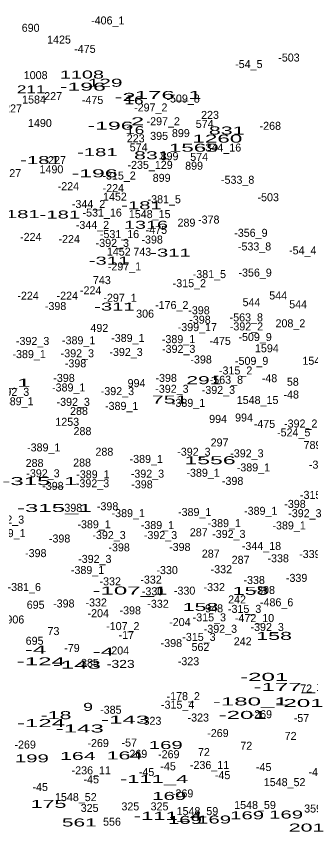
# Model space of a CAD drawing. Extents: x -660434 to -656144, y -997850 to -994016.
# Drawn here: x -658565.3 to -658418.1, y -996493.8 to -996086.2 of the extents above; entities that cross this region are included whole.
import ezdxf
from ezdxf.enums import TextEntityAlignment as Align

# ---------------------------------------------------------------- set-up
doc = ezdxf.new("R2010")
doc.units = 0
doc.header["$LTSCALE"] = 1.6
doc.layers.add('24', color=7, linetype='Continuous')

msp = doc.modelspace()

# ---------------------------------------------------------------- texts
at = {"layer": '24'}
for s, p in [('-406_1', (-658519.59, -996090.28)), ('690', (-658558.142, -996093.96)), ('1425', (-658543.954, -996099.84)), ('-475', (-658531.005, -996104.48)), ('-54_5', (-658449.047, -996112.1)), ('-503', (-658428.989, -996108.82)), ('1008', (-658555.638, -996117.62)), ('-227', (-658547.781, -996128.11)), ('1584', (-658556.454, -996129.81)), ('-475', (-658527.165, -996130.03)), ('-509_8', (-658481.932, -996129.33)), ('-227', (-658567.841, -996134.26)), ('-297_2', (-658498.084, -996133.76)), ('-297_2', (-658491.844, -996140.67)), ('223', (-658468.457, -996137.51)), ('1490', (-658553.514, -996141.54)), ('574', (-658471.127, -996141.99)), ('-268', (-658438.31, -996142.96)), ('223', (-658505.617, -996149.22)), ('395', (-658493.903, -996147.98)), ('899', (-658483.048, -996146.59)), ('574', (-658504.147, -996153.71)), ('-344_16', (-658462.679, -996153.83)), ('-227', (-658545.861, -996160.09)), ('899', (-658488.708, -996158.13)), ('574', (-658473.877, -996158.48)), ('1490', (-658547.754, -996164.69)), ('-235_129', (-658498.421, -996162.49)), ('899', (-658476.418, -996162.92)), ('-227', (-658568.231, -996166.62)), ('-315_2', (-658513.926, -996167.82)), ('899', (-658492.648, -996168.97)), ('-224', (-658539.269, -996173.13)), ('-533_8', (-658454.642, -996169.93)), ('-224', (-658516.799, -996174.09)), ('1452', (-658516.004, -996178.38)), ('-381_5', (-658491.346, -996179.65)), ('-503', (-658439.359, -996178.66)), ('-344_2', (-658529.201, -996182.04)), ('-531_16', (-658522.375, -996186.32)), ('1548_15', (-658498.626, -996187.08)), ('-378', (-658469.081, -996189.81)), ('-344_2', (-658527.241, -996192.5)), ('289', (-658480.233, -996191.35)), ('-531_16', (-658513.725, -996197.07)), ('-475', (-658495.285, -996194.95)), ('-356_9', (-658448.023, -996196.44)), ('-224', (-658558.079, -996198.49)), ('-224', (-658538.879, -996199.55)), ('-392_3', (-658517.308, -996201.48)), ('-398', (-658497.39, -996199.81)), ('1452', (-658514.084, -996205.84)), ('743', (-658502.337, -996205.93)), ('-533_8', (-658446.192, -996203.25)), ('-54_4', (-658422.091, -996205.2)), ('-297_1', (-658511.227, -996213.23)), ('-381_5', (-658468.786, -996217.08)), ('-356_9', (-658445.903, -996216.32)), ('743', (-658522.547, -996220.07)), ('-315_2', (-658478.796, -996221.61)), ('-224', (-658528.129, -996225.18)), ('-224', (-658559.429, -996227.87)), ('-224', (-658539.839, -996227.87)), ('-297_1', (-658513.437, -996228.89)), ('544', (-658434.376, -996227.75)), ('-398', (-658545.68, -996233.04)), ('-176_2', (-658487.597, -996232.52)), ('544', (-658447.716, -996231.11)), ('544', (-658424.396, -996232.16)), ('306', (-658500.927, -996236.85)), ('-398', (-658473.96, -996235.14)), ('-563_8', (-658450.328, -996238.68)), ('-398', (-658473.48, -996239.86)), ('208_2', (-658428.259, -996241.67)), ('492', (-658523.797, -996243.99)), ('-399_17', (-658474.801, -996243.57)), ('-392_2', (-658450.228, -996243.22)), ('-392_3', (-658557.168, -996250.5)), ('-389_1', (-658534.132, -996250.15)), ('-389_1', (-658509.552, -996249)), ('-389_1', (-658484.212, -996249.58)), ('-475', (-658463.405, -996250.46)), ('-509_9', (-658445.907, -996248.53)), ('-392_3', (-658484.118, -996254.45)), ('1594', (-658440.02, -996254.14)), ('-389_1', (-658558.902, -996257.07)), ('-392_3', (-658534.798, -996256.65)), ('-392_3', (-658510.448, -996255.99)), ('-398', (-658535.7, -996261.66)), ('-398', (-658472.91, -996259.74)), ('-509_9', (-658447.637, -996260.44)), ('1548_24', (-658411.847, -996260.39)), ('-315_2', (-658455.656, -996265.24)), ('-398', (-658541.46, -996268.96)), ('994', (-658505.193, -996271.55)), ('-398', (-658490.38, -996268.96)), ('-563_8', (-658460.288, -996269.88)), ('-48', (-658438.709, -996269.11)), ('58', (-658427.047, -996270.88)), ('-389_1', (-658539.122, -996273.73)), ('-392_3', (-658514.768, -996275.55)), ('-392_3', (-658487.498, -996274.4)), ('-392_3', (-658464.268, -996274.97)), ('-392_3', (-658567.188, -996275.93)), ('-48', (-658427.859, -996277.27)), ('-389_1', (-658565.042, -996280.65)), ('-392_3', (-658536.848, -996280.93)), ('-389_1', (-658512.622, -996282.95)), ('-389_1', (-658479.212, -996281.42)), ('1548_15', (-658444.676, -996280)), ('288', (-658533.977, -996285.47)), ('1253', (-658539.85, -996290.91)), ('994', (-658464.413, -996289.44)), ('994', (-658451.453, -996288.76)), ('-392_2', (-658423.098, -996291.76)), ('288', (-658532.237, -996295.57)), ('-475', (-658441.235, -996291.94)), ('-524_5', (-658426.607, -996296.19)), ('-389_1', (-658551.602, -996303.7)), ('297', (-658463.688, -996301.22)), ('789', (-658417.208, -996302.48)), ('288', (-658521.277, -996305.85)), ('-392_3', (-658476.518, -996305.87)), ('-392_3', (-658450.018, -996306.64)), ('288', (-658556.177, -996311.47)), ('288', (-658532.427, -996311.28)), ('-389_1', (-658500.332, -996309.46)), ('-374_3', (-658410.692, -996312.31)), ('-389_1', (-658471.922, -996316.37)), ('-389_1', (-658446.762, -996313.69)), ('-392_3', (-658551.978, -996316.63)), ('-389_1', (-658527.022, -996317.14)), ('-392_3', (-658499.748, -996316.82)), ('-398', (-658457.16, -996320.43)), ('-398', (-658547.02, -996322.93)), ('-392_3', (-658527.208, -996321.62)), ('-398', (-658502.48, -996322.16)), ('-315_2', (-658415.146, -996327.43)), ('-398', (-658425.97, -996331.94)), ('-398', (-658537.72, -996333.87)), ('-398', (-658519.67, -996333.1)), ('-389_1', (-658509.342, -996336.54)), ('-389_1', (-658476.122, -996335.97)), ('-389_1', (-658443.102, -996335.39)), ('-392_3', (-658421.028, -996336.58)), ('-392_3', (-658569.708, -996339.77)), ('-389_1', (-658526.432, -996342.11)), ('-389_1', (-658494.752, -996342.5)), ('-389_1', (-658461.342, -996341.54)), ('-389_1', (-658428.912, -996342.69)), ('-389_1', (-658569.012, -996346.53)), ('-392_3', (-658518.948, -996347.52)), ('-392_3', (-658493.218, -996347.52)), ('287', (-658474.093, -996346.11)), ('-392_3', (-658459.048, -996346.95)), ('-398', (-658543.67, -996349.23)), ('-344_18', (-658442.724, -996352.95)), ('-398', (-658555.58, -996356.54)), ('-398', (-658513.91, -996353.65)), ('-398', (-658483.57, -996353.46)), ('287', (-658468.083, -996356.78)), ('-339', (-658418.54, -996357)), ('-392_3', (-658526.058, -996359.43)), ('287', (-658453.163, -996359.88)), ('-338', (-658434.375, -996359.11)), ('-389_1', (-658529.692, -996364.97)), ('-330', (-658489.899, -996365.03)), ('-332', (-658462.795, -996364.58)), ('-339', (-658425.16, -996368.91)), ('-332', (-658518.355, -996370.63)), ('-332', (-658497.935, -996369.76)), ('-338', (-658446.375, -996369.97)), ('-381_6', (-658561.342, -996373.48)), ('-330', (-658497.189, -996375.6)), ('-330', (-658481.169, -996375.29)), ('-332', (-658466.355, -996373.51)), ('-398', (-658441.33, -996374.97)), ('-332', (-658525.365, -996381.19)), ('242', (-658454.931, -996379.68)), ('-486_6', (-658435.148, -996381.12)), ('695', (-658555.638, -996382.34)), ('-398', (-658541.56, -996381.7)), ('-398', (-658508.34, -996385.15)), ('-332', (-658494.455, -996381.86)), ('948', (-658466.397, -996384.15)), ('-315_3', (-658451.156, -996384.41)), ('906', (-658565.802, -996389.7)), ('-204', (-658524.333, -996386.57)), ('-315_3', (-658468.796, -996388.64)), ('-472_10', (-658446.209, -996389)), ('-107_2', (-658512.056, -996393.01)), ('-204', (-658483.523, -996390.99)), ('-392_3', (-658439.878, -996393.47)), ('73', (-658546.733, -996395.5)), ('-17', (-658510.29, -996397.43)), ('-392_3', (-658463.268, -996394.37)), ('695', (-658556.168, -996400.35)), ('-398', (-658487.79, -996401.48)), ('-315_3', (-658473.986, -996398.43)), ('242', (-658452.121, -996400.62)), ('-79', (-658537.485, -996403.97)), ('-204', (-658514.253, -996405.2)), ('562', (-658473.243, -996403.46)), ('-385', (-658529.375, -996411.4)), ('-323', (-658479.225, -996410.57)), ('72', (-658420.383, -996424.19)), ('-178_2', (-658481.842, -996428.03)), ('-315_4', (-658484.64, -996432.3)), ('-385', (-658518.045, -996434.83)), ('-269', (-658442.805, -996437.06)), ('-323', (-658498.135, -996440.34)), ('-323', (-658474.325, -996438.71)), ('-57', (-658422.721, -996438.95)), ('-269', (-658464.495, -996446.47)), ('72', (-658428.163, -996447.91)), ('-269', (-658560.885, -996452.23)), ('-269', (-658524.405, -996451.47)), ('-57', (-658508.841, -996451.24)), ('72', (-658450.333, -996452.81)), ('-269', (-658505.205, -996456.84)), ('-269', (-658489.075, -996457.04)), ('72', (-658471.513, -996455.98)), ('-45', (-658489.429, -996463.08)), ('-236_11', (-658468.695, -996462.43)), ('-236_11', (-658527.835, -996465.12)), ('-45', (-658500.179, -996465.96)), ('-45', (-658441.619, -996463.46)), ('-45', (-658415.369, -996465.96)), ('-45', (-658527.829, -996469.61)), ('-45', (-658462.169, -996467.5)), ('1548_52', (-658431.152, -996471)), ('-45', (-658553.369, -996473.45)), ('1548_52', (-658535.552, -996478.5)), ('-269', (-658482.165, -996476.63)), ('325', (-658508.297, -996483.13)), ('325', (-658493.707, -996483.13)), ('1548_59', (-658445.957, -996482.42)), ('325', (-658528.647, -996483.9)), ('1548_59', (-658474.757, -996485.5)), ('359', (-658416.913, -996484.2)), ('556', (-658517.483, -996490.77))]:
    msp.add_text(s, height=4, dxfattribs=at).set_placement(p, align=Align.CENTER)
for s, width, p in [('1108', 1.85, (-658532.5, -996117.32)), ('211', 1.6, (-658557.904, -996124.73)), ('-196', 2.15, (-658532.049, -996123.38)), ('129', 1.95, (-658520.913, -996121.43)), ('-2', 2.2, (-658510.954, -996128.51)), ('-176_1', 2.25, (-658491.417, -996127.54)), ('16', 1.6, (-658506.463, -996130.21)), ('-2', 2.2, (-658506.634, -996140.7)), ('-196', 2.15, (-658518.219, -996142.88)), ('16', 1.6, (-658506.083, -996145.09)), ('831', 2, (-658460.107, -996145.3)), ('1260', 2.1, (-658464.789, -996149.35)), ('-181', 1.9, (-658524.797, -996156.12)), ('1569', 2.1, (-658476.567, -996153.9)), ('-181', 1.9, (-658553.217, -996160.06)), ('831', 2, (-658497.537, -996157.68)), ('-196', 2.15, (-658526.189, -996166.69)), ('-181', 1.9, (-658502.727, -996182.67)), ('-181', 1.9, (-658563.747, -996187.09)), ('-181', 1.9, (-658543.527, -996187.29)), ('1316', 1.85, (-658500.469, -996192.42)), ('-311', 1.9, (-658488.227, -996206.33)), ('-311', 1.9, (-658518.947, -996210.36)), ('-311', 1.9, (-658516.257, -996233.31)), ('-315_1', 2.25, (-658576.997, -996271.37)), ('291', 1.95, (-658471.543, -996270.09)), ('751', 2, (-658488.623, -996279.76)), ('1556', 2.15, (-658468.433, -996310.11)), ('-315_1', 2.25, (-658553.567, -996320.54)), ('-315_1', 2.25, (-658546.277, -996333.99)), ('-107_1', 2.25, (-658508.499, -996375.24)), ('158', 2, (-658448.157, -996375.39)), ('158', 2, (-658473.207, -996383.45)), ('158', 2, (-658436.397, -996397.9)), ('-4', 2.25, (-658555.69, -996404.76)), ('-4', 2.25, (-658521.75, -996405.72)), ('-124', 2.25, (-658553.056, -996410.64)), ('-143', 2.25, (-658535.016, -996412.3)), ('-323', 1.3, (-658513.08, -996411.92)), ('-201', 2.25, (-658441.367, -996418.39)), ('-177_1', 2.25, (-658427.967, -996423.39)), ('9', 1.65, (-658529.426, -996433.39)), ('-180_1', 2.25, (-658448.304, -996430.67)), ('-201', 2.25, (-658423.707, -996431.46)), ('-18', 2, (-658545.461, -996437.53)), ('-201', 2.25, (-658452.117, -996437.41)), ('-124', 2.25, (-658552.966, -996441.47)), ('-143', 2.25, (-658510.916, -996439.77)), ('-143', 2.25, (-658533.576, -996444.19)), ('169', 1.9, (-658490.577, -996452.45)), ('164', 2, (-658534.538, -996457.92)), ('164', 2, (-658511.208, -996457.63)), ('199', 1.9, (-658557.537, -996459.12)), ('-111_4', 2.05, (-658496.409, -996469.41)), ('169', 1.9, (-658488.857, -996477.9)), ('175', 2, (-658549.173, -996481.88)), ('169', 1.9, (-658449.907, -996487.58)), ('169', 1.9, (-658430.417, -996487.2)), ('561', 1.95, (-658533.823, -996491.16)), ('-111_4', 2.05, (-658489.499, -996487.85)), ('169', 1.9, (-658481.007, -996489.88)), ('169', 1.9, (-658466.417, -996489.69)), ('201', 2, (-658420.184, -996493.72))]:
    msp.add_text(s, height=4, dxfattribs=dict(at, width=width)).set_placement(p, align=Align.CENTER)

doc.saveas('drawing.dxf')
